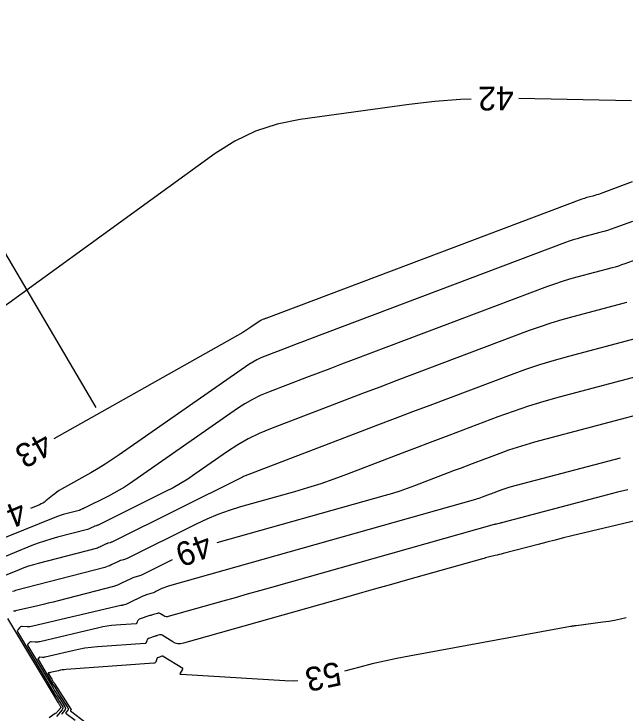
# Model space of a CAD drawing. Extents: x 2384780 to 2405861, y 547869 to 573706.
# Drawn here: x 2390220.5 to 2390271.7, y 552537.6 to 552596.3 of the extents above; entities that cross this region are included whole.
import ezdxf

# ---------------------------------------------------------------- set-up
doc = ezdxf.new("R2010")
doc.units = 0
for name, color, linetype in [('Old_Level_60', 7, 'Continuous'), ('Old_Level_61', 7, 'Continuous'), ('Prop Buffer Zone 2', 7, 'Continuous')]:
    doc.layers.add(name, color=color, linetype=linetype)

msp = doc.modelspace()

# ---------------------------------------------------------------- linework, layer by layer
at = {"layer": 'Old_Level_60'}
for points in [[(2390258.81725, 552589.1495), (2390257.905, 552589.11425), (2390255.76325, 552588.947), (2390253.62675, 552588.6955), (2390244.47775, 552587.4365), (2390242.562, 552587.05525), (2390240.73575, 552586.45125), (2390238.999, 552585.6245), (2390237.35175, 552584.575), (2390213.2345, 552567.10425)], [(2390272.25425, 552588.99275), (2390262.81625, 552589.1835)], [(2390272.30875, 552582.22275), (2390269.6165, 552581.2165), (2390269.46725, 552581.163), (2390269.317, 552581.113), (2390269.1655, 552581.06675), (2390269.01275, 552581.0245), (2390268.512, 552580.89175), (2390268.40525, 552580.862), (2390268.29925, 552580.82975), (2390268.194, 552580.7945), (2390268.08975, 552580.75675), (2390241.60725, 552570.772), (2390241.56, 552570.754), (2390241.5125, 552570.736), (2390241.465, 552570.718), (2390241.41775, 552570.7), (2390241.263, 552570.64075), (2390241.23025, 552570.627), (2390241.19875, 552570.6115), (2390241.168, 552570.594), (2390241.1385, 552570.57475), (2390240.361, 552570.0345), (2390240.193, 552569.9205), (2390240.02275, 552569.81075), (2390239.84975, 552569.705), (2390239.6745, 552569.60325), (2390223.852, 552560.674)], [(2390272.31525, 552578.9035), (2390270.86, 552578.35975), (2390270.547, 552578.247), (2390270.23125, 552578.14225), (2390269.91325, 552578.04525), (2390269.59275, 552577.95625), (2390268.0265, 552577.5415), (2390267.69225, 552577.4485), (2390267.3605, 552577.347), (2390267.03175, 552577.23725), (2390266.7055, 552577.119), (2390245.2695, 552569.03675), (2390244.75575, 552568.84275), (2390244.24225, 552568.648), (2390243.72925, 552568.45275), (2390243.21625, 552568.25675), (2390241.54075, 552567.61575), (2390241.18725, 552567.468), (2390240.8445, 552567.3), (2390240.5125, 552567.11125), (2390240.1915, 552566.90225), (2390229.31925, 552559.3445), (2390228.73825, 552558.9505), (2390228.14825, 552558.5705), (2390227.54975, 552558.2045), (2390226.9425, 552557.85225), (2390224.479, 552556.462), (2390224.2865, 552556.3475), (2390224.0995, 552556.22475), (2390223.918, 552556.09375), (2390223.7425, 552555.9545), (2390223.178, 552555.48625), (2390223.054, 552555.391), (2390222.92375, 552555.306), (2390222.7875, 552555.2315), (2390222.645, 552555.167), (2390221.89475, 552554.862)], [(2390271.84925, 552572.11325), (2390271.63, 552572.05225), (2390267.3185, 552570.91075), (2390266.39825, 552570.6545), (2390265.4855, 552570.37525), (2390264.58, 552570.07275), (2390263.682, 552569.74725), (2390252.59375, 552565.5665), (2390251.1475, 552565.02025), (2390249.702, 552564.47225), (2390248.25725, 552563.92225), (2390246.813, 552563.37075), (2390241.9845, 552561.523), (2390241.04425, 552561.13025), (2390240.13275, 552560.683), (2390239.25, 552560.18125), (2390238.396, 552559.625), (2390235.654, 552557.719), (2390235.05975, 552557.32175), (2390234.45225, 552556.947), (2390233.83125, 552556.595), (2390233.197, 552556.26525), (2390227.5475, 552553.459), (2390227.51525, 552553.44375), (2390227.48275, 552553.4305), (2390227.4495, 552553.4185), (2390227.4155, 552553.408), (2390227.304, 552553.3765), (2390227.28025, 552553.36925), (2390227.257, 552553.361), (2390227.23425, 552553.3515), (2390227.21175, 552553.341), (2390226.92775, 552553.20075), (2390226.86625, 552553.17225), (2390226.8035, 552553.14725), (2390226.73975, 552553.12525), (2390226.6745, 552553.1065), (2390224.138, 552552.446), (2390223.5975, 552552.29575), (2390223.0625, 552552.128), (2390222.5335, 552551.94275), (2390222.01025, 552551.74), (2390218.99975, 552550.51575)], [(2390272.64875, 552569.10025), (2390266.9645, 552567.59525), (2390265.75125, 552567.25775), (2390264.54775, 552566.8895), (2390263.35425, 552566.49075), (2390262.17025, 552566.0615), (2390255.35225, 552563.49075), (2390253.8915, 552562.939), (2390252.4315, 552562.3855), (2390250.97225, 552561.83), (2390249.5135, 552561.27275), (2390239.73025, 552557.529), (2390239.71575, 552557.523), (2390239.702, 552557.516), (2390239.6885, 552557.5085), (2390239.6755, 552557.5), (2390239.6335, 552557.47075), (2390239.6245, 552557.46475), (2390239.61525, 552557.459), (2390239.60575, 552557.45375), (2390239.596, 552557.44875), (2390228.7615, 552552.06675), (2390228.71125, 552552.043), (2390228.66025, 552552.022), (2390228.60825, 552552.00325), (2390228.555, 552551.987), (2390228.3805, 552551.93775), (2390228.34325, 552551.9265), (2390228.30675, 552551.91325), (2390228.271, 552551.8985), (2390228.23575, 552551.88225), (2390227.79125, 552551.6625), (2390227.695, 552551.618), (2390227.59675, 552551.5785), (2390227.49675, 552551.544), (2390227.39475, 552551.51475), (2390222.54325, 552550.25175), (2390222.134, 552550.138), (2390221.72925, 552550.011), (2390221.32875, 552549.87075), (2390220.93275, 552549.71725), (2390219.337, 552549.06825)], [(2390273.6675, 552566.14825), (2390266.19775, 552564.17075), (2390264.897, 552563.80875), (2390263.607, 552563.41375), (2390262.32725, 552562.98625), (2390261.058, 552562.52625), (2390256.929, 552560.9695), (2390256.0445, 552560.63525), (2390255.16025, 552560.3), (2390254.2765, 552559.96375), (2390253.39325, 552559.62625), (2390248.3705, 552557.70425), (2390247.29025, 552557.30475), (2390246.2015, 552556.93), (2390245.10475, 552556.58025), (2390243.9995, 552556.25525), (2390239.48875, 552554.98425), (2390238.5305, 552554.69), (2390237.589, 552554.35225), (2390236.66425, 552553.971), (2390235.7565, 552553.546), (2390229.97575, 552550.6745), (2390229.9075, 552550.64225), (2390229.83775, 552550.61375), (2390229.76675, 552550.58825), (2390229.69475, 552550.566), (2390229.45675, 552550.499), (2390229.40625, 552550.4835), (2390229.35675, 552550.46575), (2390229.30775, 552550.44575), (2390229.26, 552550.42325), (2390228.6545, 552550.12425), (2390228.5235, 552550.0635), (2390228.39, 552550.00975), (2390228.25375, 552549.963), (2390228.115, 552549.923), (2390220.63675, 552547.97625), (2390220.514, 552547.942), (2390220.3925, 552547.904)], [(2390274.686, 552563.19625), (2390264.1175, 552560.39825), (2390263.3835, 552560.194), (2390262.6555, 552559.97125), (2390261.9335, 552559.73), (2390261.21725, 552559.47025), (2390258.8875, 552558.59175), (2390258.38825, 552558.40325), (2390257.8895, 552558.21425), (2390257.39075, 552558.0245), (2390256.89225, 552557.834), (2390254.05825, 552556.7495), (2390253.4485, 552556.524), (2390252.83425, 552556.3125), (2390252.21525, 552556.11525), (2390251.59175, 552555.932), (2390237.50775, 552551.9635)], [(2390284.55775, 552556.676), (2390267.25375, 552552.55675), (2390266.5475, 552552.38625), (2390265.84225, 552552.21175), (2390265.13825, 552552.033), (2390264.435, 552551.85), (2390261.4995, 552551.077), (2390261.328, 552551.03225), (2390261.156, 552550.9885), (2390260.984, 552550.946), (2390260.81175, 552550.90425), (2390260.24825, 552550.7695), (2390260.1275, 552550.74025), (2390260.00725, 552550.7095), (2390259.88725, 552550.67775), (2390259.76775, 552550.6445), (2390253.47825, 552548.8725), (2390252.1305, 552548.49275), (2390250.783, 552548.11225), (2390249.4355, 552547.73175), (2390248.088, 552547.3505), (2390234.705, 552543.56325), (2390234.46925, 552543.52025), (2390234.2405, 552543.527), (2390234.01875, 552543.583), (2390233.80375, 552543.6885), (2390232.92125, 552544.23175), (2390232.86825, 552544.258), (2390232.81325, 552544.27175), (2390232.7565, 552544.2735), (2390232.69825, 552544.263), (2390232.505, 552544.2085), (2390232.4635, 552544.1965), (2390232.4225, 552544.184), (2390232.3815, 552544.171), (2390232.3405, 552544.1575), (2390231.76425, 552543.96225), (2390231.74325, 552543.953), (2390231.725, 552543.94), (2390231.7095, 552543.924), (2390231.69725, 552543.9045), (2390231.66125, 552543.835), (2390231.654, 552543.82), (2390231.64725, 552543.80475), (2390231.641, 552543.78925), (2390231.63525, 552543.7735), (2390231.58325, 552543.61975), (2390231.56925, 552543.5905), (2390231.54925, 552543.569), (2390231.52325, 552543.55525), (2390231.4915, 552543.54875), (2390227.4915, 552543.26075), (2390226.9645, 552543.21225), (2390226.4405, 552543.143), (2390225.92, 552543.05275), (2390225.4025, 552542.94175), (2390223.105, 552542.4005), (2390223.05, 552542.38975), (2390222.9945, 552542.3825), (2390222.939, 552542.37925), (2390222.88275, 552542.38), (2390222.67925, 552542.38975), (2390222.65125, 552542.388), (2390222.626, 552542.38025), (2390222.60325, 552542.3665), (2390222.5835, 552542.3465), (2390222.52325, 552542.2715), (2390222.51325, 552542.25525), (2390222.509, 552542.2385), (2390222.51075, 552542.2215), (2390222.5185, 552542.204)], [(2390271.9405, 552556.4295), (2390271.0815, 552556.2115), (2390270.22375, 552555.98825), (2390261.455, 552553.67875), (2390261.384, 552553.66025), (2390261.313, 552553.64225), (2390261.24175, 552553.6245), (2390261.1705, 552553.60725), (2390260.9375, 552553.55175), (2390260.88775, 552553.5395), (2390260.838, 552553.52675), (2390260.78825, 552553.51375), (2390260.73875, 552553.5), (2390242.09, 552548.24575), (2390241.06875, 552547.958), (2390240.0475, 552547.66975), (2390239.0265, 552547.38125), (2390238.0055, 552547.0925), (2390233.43725, 552545.79975), (2390233.3405, 552545.782), (2390233.2465, 552545.78475), (2390233.15525, 552545.80775), (2390233.06675, 552545.85125), (2390232.78275, 552546.02625), (2390232.72075, 552546.0565), (2390232.657, 552546.07275), (2390232.59125, 552546.07475), (2390232.52325, 552546.06225), (2390232.18375, 552545.96675), (2390232.11125, 552545.94575), (2390232.039, 552545.92375), (2390231.967, 552545.901), (2390231.89525, 552545.877), (2390231.00025, 552545.574), (2390230.967, 552545.55925), (2390230.938, 552545.539), (2390230.914, 552545.5135), (2390230.89425, 552545.48275), (2390230.831, 552545.36025), (2390230.82275, 552545.343), (2390230.815, 552545.32575), (2390230.80775, 552545.308), (2390230.8015, 552545.29), (2390230.7815, 552545.231), (2390230.776, 552545.21975), (2390230.76825, 552545.2115), (2390230.7585, 552545.20625), (2390230.74625, 552545.20375), (2390229.04425, 552545.08125), (2390228.68075, 552545.04775), (2390228.31925, 552545), (2390227.96, 552544.93775), (2390227.603, 552544.861), (2390222.659, 552543.6965), (2390222.5655, 552543.678), (2390222.4715, 552543.666), (2390222.377, 552543.6605), (2390222.28175, 552543.66175), (2390221.936, 552543.678), (2390221.88825, 552543.67525), (2390221.84525, 552543.662), (2390221.80675, 552543.6385), (2390221.77325, 552543.60475), (2390221.67075, 552543.47725), (2390221.65375, 552543.44975), (2390221.64675, 552543.4215), (2390221.64975, 552543.3925), (2390221.66275, 552543.36275), (2390223.784, 552539.82325), (2390223.906, 552539.62175), (2390224.02925, 552539.421), (2390224.15425, 552539.22125), (2390224.281, 552539.0225), (2390224.7605, 552538.2755), (2390224.802, 552538.18725), (2390224.81225, 552538.101), (2390224.7915, 552538.0165), (2390224.73925, 552537.93425), (2390224.5175, 552537.668), (2390224.4835, 552537.6125)], [(2390233.76975, 552550.56375), (2390231.19, 552549.282), (2390231.1035, 552549.2415), (2390231.01525, 552549.20525), (2390230.9255, 552549.173), (2390230.83425, 552549.145), (2390230.53325, 552549.06025), (2390230.46925, 552549.0405), (2390230.4065, 552549.018), (2390230.34475, 552548.99275), (2390230.284, 552548.9645), (2390229.518, 552548.58575), (2390229.35225, 552548.509), (2390229.18325, 552548.441), (2390229.01075, 552548.38175), (2390228.83525, 552548.33125), (2390224.19475, 552547.12325), (2390223.77625, 552547.01575), (2390223.35725, 552546.91075), (2390222.9375, 552546.8085), (2390222.51725, 552546.70875), (2390220.63775, 552546.2695), (2390220.59575, 552546.261), (2390220.55325, 552546.25575), (2390220.51075, 552546.25325), (2390220.46775, 552546.25375)], [(2390219.97025, 552545.6485), (2390224.20425, 552538.584), (2390224.232, 552538.538), (2390224.26, 552538.4925), (2390224.2885, 552538.447), (2390224.31725, 552538.40175), (2390224.412, 552538.2545), (2390224.4265, 552538.22325), (2390224.43025, 552538.19275), (2390224.42275, 552538.16275), (2390224.4045, 552538.1335), (2390224.18375, 552537.86875), (2390224.135, 552537.814), (2390224.08275, 552537.76275), (2390224.027, 552537.71525), (2390223.968, 552537.67125), (2390223.453, 552537.315)], [(2390271.804, 552545.6935), (2390271.31575, 552545.5815), (2390270.82525, 552545.48275), (2390270.33225, 552545.3975), (2390269.83675, 552545.32525), (2390267.616, 552545.03275), (2390267.56725, 552545.0265), (2390267.5185, 552545.02), (2390267.46975, 552545.0135), (2390267.421, 552545.00725), (2390267.26175, 552544.98625), (2390267.22775, 552544.9815), (2390267.1935, 552544.97625), (2390267.15975, 552544.97075), (2390267.12575, 552544.96475), (2390253.6275, 552542.49225), (2390252.58475, 552542.29125), (2390251.5465, 552542.071), (2390250.5125, 552541.83125), (2390249.483, 552541.57225), (2390248.20575, 552541.2385)], [(2390244.3005, 552540.41375), (2390243.94275, 552540.393), (2390243.2035, 552540.409), (2390234.52325, 552540.93675), (2390234.4645, 552540.94825), (2390234.4335, 552540.97425), (2390234.43025, 552541.0145), (2390234.455, 552541.069), (2390234.61975, 552541.3325), (2390234.627, 552541.345), (2390234.6335, 552541.358), (2390234.639, 552541.37125), (2390234.64375, 552541.385), (2390234.65775, 552541.4305), (2390234.65925, 552541.43975), (2390234.658, 552541.44775), (2390234.65375, 552541.45475), (2390234.6465, 552541.46075), (2390233.0165, 552542.46425), (2390232.994, 552542.47525), (2390232.971, 552542.48125), (2390232.947, 552542.482), (2390232.9225, 552542.4775), (2390232.84075, 552542.4545), (2390232.8235, 552542.4495), (2390232.806, 552542.44425), (2390232.78875, 552542.43875), (2390232.7715, 552542.433), (2390232.52825, 552542.3505), (2390232.51925, 552542.3465), (2390232.51175, 552542.34125), (2390232.50525, 552542.3345), (2390232.5, 552542.32625), (2390232.48475, 552542.29675), (2390232.48175, 552542.2905), (2390232.47875, 552542.284), (2390232.47625, 552542.2775), (2390232.47375, 552542.271), (2390232.3865, 552542.01275), (2390232.363, 552541.96375), (2390232.32925, 552541.9275), (2390232.286, 552541.90425), (2390232.2325, 552541.8935), (2390224.872, 552541.36375), (2390224.71325, 552541.349), (2390224.5555, 552541.32825), (2390224.39875, 552541.301), (2390224.24275, 552541.2675), (2390223.55075, 552541.1045), (2390223.53425, 552541.10125), (2390223.5175, 552541.09925), (2390223.50075, 552541.09825), (2390223.484, 552541.0985), (2390223.4225, 552541.10125), (2390223.41425, 552541.10075), (2390223.4065, 552541.0985), (2390223.39975, 552541.09425), (2390223.39375, 552541.08825), (2390223.3755, 552541.06575), (2390223.3725, 552541.06075), (2390223.37125, 552541.05575), (2390223.372, 552541.05075), (2390223.37425, 552541.0455)], [(2390222.5185, 552542.204), (2390223.574, 552540.443), (2390223.743, 552540.1635), (2390223.914, 552539.88525), (2390224.08725, 552539.6085), (2390224.26275, 552539.333), (2390225.019, 552538.15475), (2390225.04325, 552538.103), (2390225.0495, 552538.05225), (2390225.03725, 552538.00275), (2390225.0065, 552537.95425), (2390224.87625, 552537.798), (2390224.85625, 552537.7655), (2390224.85175, 552537.73475), (2390224.86325, 552537.70575), (2390224.89025, 552537.67875), (2390225.62525, 552537.1285)], [(2390223.37425, 552541.0455), (2390223.6655, 552540.55925), (2390223.72975, 552540.453), (2390223.79475, 552540.34725), (2390223.86075, 552540.242), (2390223.92725, 552540.13725), (2390225.2775, 552538.03425), (2390225.28475, 552538.01875), (2390225.2865, 552538.00375), (2390225.28275, 552537.989), (2390225.27375, 552537.9745), (2390225.235, 552537.928), (2390225.229, 552537.91825), (2390225.22775, 552537.909), (2390225.231, 552537.9005), (2390225.239, 552537.8925), (2390226.5585, 552536.9045)]]:
    msp.add_lwpolyline(points, dxfattribs=at)
at = {"layer": 'Old_Level_61'}
for points in [[(2390272.9035, 552575.80175), (2390271.6785, 552575.344), (2390271.41475, 552575.249), (2390271.149, 552575.16075), (2390270.88125, 552575.07925), (2390270.6115, 552575.00425), (2390267.6725, 552574.22625), (2390267.04525, 552574.0515), (2390266.423, 552573.86125), (2390265.80575, 552573.655), (2390265.19375, 552573.433), (2390248.93175, 552567.30175), (2390247.95175, 552566.9315), (2390246.97225, 552566.56025), (2390245.99325, 552566.1875), (2390245.0145, 552565.81375), (2390241.8185, 552564.59075), (2390241.144, 552564.309), (2390240.49025, 552563.98825), (2390239.857, 552563.6285), (2390239.24475, 552563.2295), (2390230.177, 552556.92625), (2390229.75475, 552556.644), (2390229.323, 552556.37775), (2390228.88175, 552556.1275), (2390228.431, 552555.89325), (2390226.33325, 552554.85125), (2390226.31925, 552554.8445), (2390226.30525, 552554.83875), (2390226.29075, 552554.8335), (2390226.276, 552554.829), (2390226.2275, 552554.8155), (2390226.21725, 552554.81225), (2390226.20725, 552554.80875), (2390226.19725, 552554.8045), (2390226.1875, 552554.8), (2390226.06425, 552554.739), (2390226.0375, 552554.72675), (2390226.0105, 552554.71575), (2390225.98275, 552554.70625), (2390225.9545, 552554.69825), (2390224.85325, 552554.4115), (2390224.61875, 552554.34625), (2390224.3865, 552554.2735), (2390224.157, 552554.193), (2390223.92975, 552554.105), (2390218.6625, 552551.96325)], [(2390271.286, 552559.07425), (2390262.03725, 552556.62575), (2390261.87, 552556.57925), (2390261.70425, 552556.5285), (2390261.53975, 552556.47375), (2390261.3765, 552556.4145), (2390260.84575, 552556.21425), (2390260.732, 552556.1715), (2390260.6185, 552556.12825), (2390260.50475, 552556.085), (2390260.39125, 552556.04175), (2390259.74575, 552555.79475), (2390259.60675, 552555.74325), (2390259.46675, 552555.69525), (2390259.326, 552555.65025), (2390259.18375, 552555.6085), (2390233.5345, 552548.38125), (2390233.37275, 552548.3315), (2390233.214, 552548.27475), (2390233.058, 552548.21025), (2390232.90475, 552548.1385), (2390232.404, 552547.88975), (2390232.2995, 552547.84075), (2390232.19275, 552547.79675), (2390232.08425, 552547.758), (2390231.97375, 552547.724), (2390231.60975, 552547.62125), (2390231.53225, 552547.5975), (2390231.45625, 552547.57025), (2390231.3815, 552547.53975), (2390231.30825, 552547.5055), (2390230.103, 552546.90975), (2390230.043, 552546.882), (2390229.98175, 552546.8575), (2390229.9195, 552546.83625), (2390229.85625, 552546.81775), (2390229.647, 552546.7635), (2390229.602, 552546.752), (2390229.55725, 552546.74075), (2390229.51225, 552546.72975), (2390229.467, 552546.719), (2390222.07175, 552544.98975), (2390221.956, 552544.967), (2390221.8395, 552544.95225), (2390221.72225, 552544.9455), (2390221.604, 552544.947), (2390221.1925, 552544.96625), (2390221.12525, 552544.96225), (2390221.0645, 552544.94375), (2390221.0105, 552544.91075), (2390220.963, 552544.863), (2390220.81825, 552544.68325), (2390220.79425, 552544.64425), (2390220.7845, 552544.60425), (2390220.78875, 552544.56325), (2390220.807, 552544.52125), (2390223.99425, 552539.20375), (2390224.069, 552539.08), (2390224.14475, 552538.95675), (2390224.2215, 552538.83425), (2390224.299, 552538.71225), (2390224.55425, 552538.3145), (2390224.594, 552538.23025), (2390224.604, 552538.148), (2390224.584, 552538.06725), (2390224.534, 552537.9885), (2390224.07175, 552537.4335)]]:
    msp.add_lwpolyline(points, dxfattribs=at)
at = {"layer": 'Prop Buffer Zone 2'}
msp.add_lwpolyline([(2390227.39692, 552563.29867), (2390217.75225, 552579.63075), (2390209.993, 552591.51075), (2390207.98675, 552599.97025), (2390193.91875, 552623.3225), (2390165.50625, 552642.3085), (2390142.40425, 552654.89925)], dxfattribs=at)

# ---------------------------------------------------------------- texts
at = {"layer": 'Old_Level_60'}
for s, rotation, p in [('42', 180.4857, (2390262.37425, 552590.21)), ('43', 209.4381, (2390222.997, 552561.33975)), ('44', 202.1929389, (2390221.03475, 552555.59375)), ('49', 200.5299306, (2390236.63425, 552552.8255)), ('53', 191.9251833, (2390247.67425, 552542.05125))]:
    msp.add_text(s, height=2, rotation=rotation, dxfattribs=at).set_placement(p)

doc.saveas('drawing.dxf')
